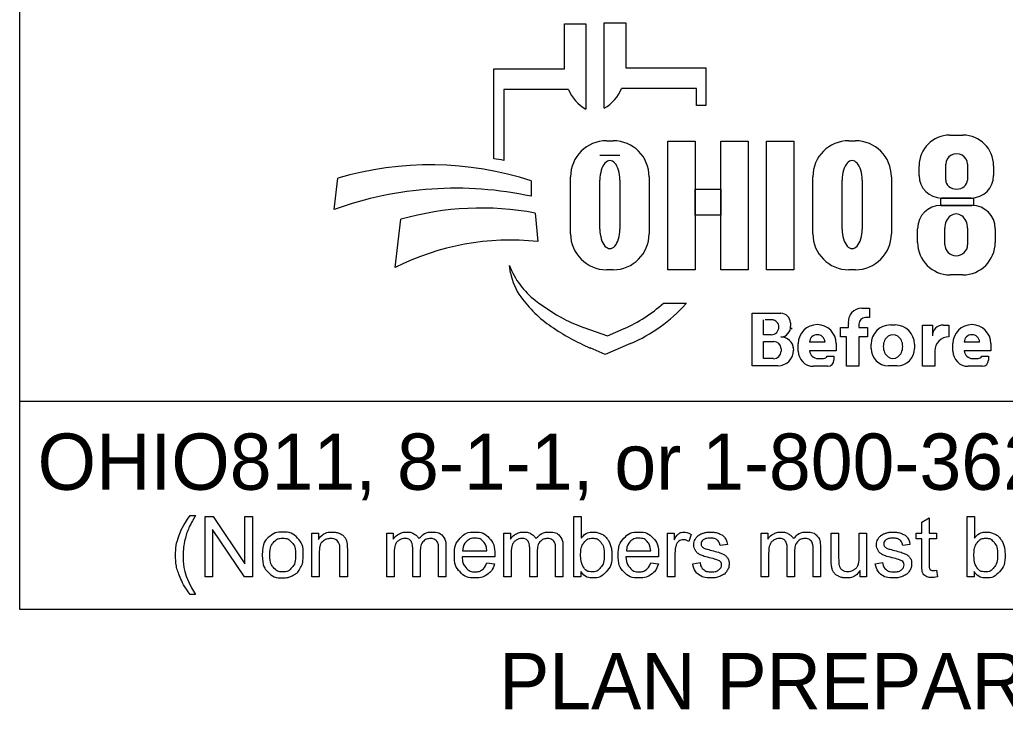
# Model space of a CAD drawing. Extents: x 0 to 84, y -106 to 22.
# Drawn here: x 2.912 to 5.365, y 2.808 to 4.523 of the extents above; entities that cross this region are included whole.
import ezdxf

# ---------------------------------------------------------------- set-up
doc = ezdxf.new("R2010")
doc.units = 0
doc.layers.add('CS-ANNO', color=7, linetype='Continuous')
doc.layers.add('CS-ANNO-MATC', color=7, linetype='Continuous')

msp = doc.modelspace()

# ---------------------------------------------------------------- linework, layer by layer
at = {"layer": 'CS-ANNO'}
for p, q in [((2.9116, 3.0559), (2.9116, 5.3934)), ((7.1616, 3.5737), (2.9116, 3.5737)), ((7.1616, 3.0559), (2.9116, 3.0559))]:
    msp.add_line(p, q, dxfattribs=at)
at = {"layer": 'CS-ANNO-MATC'}
for p, q in [((4.367, 4.3031), (4.367, 4.5152)), ((4.367, 4.5152), (4.4206, 4.5152)), ((4.4206, 4.5152), (4.4206, 4.4037)), ((4.2676, 4.4014), (4.2676, 4.5129)), ((4.2676, 4.5129), (4.3213, 4.5129)), ((4.3213, 4.5129), (4.3213, 4.3008)), ((4.0917, 4.1775), (4.0917, 4.4014)), ((4.0917, 4.4014), (4.2676, 4.4014)), ((4.4206, 4.4037), (4.6198, 4.4037)), ((4.6198, 4.4037), (4.6198, 4.3099)), ((4.1169, 4.3499), (4.1169, 4.1731)), ((4.2781, 4.3499), (4.1169, 4.3499)), ((4.5966, 4.3523), (4.4102, 4.3523)), ((4.5966, 4.3099), (4.5966, 4.3523)), ((4.6198, 4.3099), (4.5966, 4.3099)), ((4.3726, 4.2222), (4.3892, 4.2222)), ((4.9757, 4.2222), (4.9922, 4.2222)), ((5.2272, 4.2362), (5.2599, 4.2362)), ((4.4059, 4.1852), (4.3561, 4.1852)), ((5.1509, 4.1356), (5.1509, 4.1599)), ((5.2171, 4.1242), (5.2171, 4.1635)), ((5.2712, 4.1635), (5.2712, 4.1242)), ((5.3363, 4.1599), (5.3363, 4.1356)), ((3.6943, 4.0512), (3.7037, 4.1293)), ((4.185, 4.1228), (4.185, 4.084)), ((4.2832, 3.9907), (4.2832, 4.1327)), ((4.3561, 4.0021), (4.3561, 4.1245)), ((4.4059, 4.1245), (4.4059, 4.0021)), ((4.4786, 4.1327), (4.4786, 3.9907)), ((4.8862, 3.9907), (4.8862, 4.1327)), ((4.9591, 4.0021), (4.9591, 4.1245)), ((5.0089, 4.1245), (5.0089, 4.0021)), ((5.0817, 4.1327), (5.0817, 3.9907)), ((5.2803, 4.0796), (5.2069, 4.0796)), ((5.2051, 4.0613), (5.2824, 4.0613)), ((3.8461, 3.9067), (3.8608, 4.0268)), ((4.1949, 4.0422), (4.2012, 3.9713)), ((5.1472, 3.9694), (5.1472, 4.0034)), ((5.2147, 3.9634), (5.2147, 4.0043)), ((5.2715, 4.0043), (5.2715, 3.9634)), ((5.3403, 4.0034), (5.3403, 3.9694)), ((4.1338, 3.8938), (4.1308, 3.9117)), ((4.3892, 3.9013), (4.3726, 3.9013)), ((4.9922, 3.9013), (4.9757, 3.9013)), ((5.2593, 3.8884), (5.2282, 3.8884)), ((4.5141, 3.8179), (4.5716, 3.8179)), ((5.008, 3.8057), (5.0275, 3.8057)), ((5.0275, 3.8057), (5.0275, 3.7827)), ((4.7354, 3.6621), (4.7354, 3.7929)), ((4.7354, 3.7929), (4.8066, 3.7929)), ((5.0275, 3.7822), (5.0173, 3.7822)), ((4.3157, 3.7575), (4.3751, 3.737)), ((4.3751, 3.737), (4.4162, 3.7548)), ((4.7634, 3.7394), (4.7634, 3.7763)), ((4.7886, 3.7763), (4.7673, 3.7763)), ((4.8304, 3.7691), (4.8304, 3.7612)), ((4.9554, 3.7343), (4.9554, 3.7573)), ((4.9554, 3.7573), (4.9747, 3.7573)), ((4.9747, 3.7573), (4.9747, 3.7677)), ((5.0008, 3.7657), (5.0008, 3.7573)), ((5.0008, 3.7573), (5.0224, 3.7573)), ((5.0224, 3.7573), (5.0224, 3.7343)), ((5.0792, 3.7638), (5.0914, 3.7638)), ((5.1595, 3.6609), (5.1595, 3.7636)), ((5.1595, 3.7636), (5.184, 3.7636)), ((5.184, 3.7636), (5.184, 3.7367)), ((5.2113, 3.7636), (5.2251, 3.7636)), ((5.2251, 3.7636), (5.2251, 3.734)), ((4.7828, 3.7394), (4.7634, 3.7394)), ((4.9703, 3.7343), (4.9554, 3.7343)), ((4.9703, 3.6609), (4.9703, 3.7343)), ((5.0224, 3.7343), (5.0008, 3.7343)), ((5.0008, 3.7343), (5.0008, 3.6609)), ((4.3691, 3.69), (4.3318, 3.7065)), ((4.4324, 3.7175), (4.3691, 3.69)), ((4.7634, 3.68), (4.7634, 3.7228)), ((4.7634, 3.7228), (4.7889, 3.7228)), ((4.85, 3.6989), (4.85, 3.7173)), ((4.9165, 3.7213), (4.878, 3.7213)), ((4.9445, 3.7173), (4.9445, 3.6997)), ((5.0314, 3.7052), (5.0314, 3.716)), ((5.1392, 3.716), (5.1392, 3.7052)), ((5.2349, 3.6989), (5.2349, 3.7173)), ((5.3015, 3.7213), (5.2629, 3.7213)), ((5.3294, 3.7173), (5.3294, 3.6997)), ((4.807, 3.7047), (4.807, 3.6983)), ((4.8384, 3.7018), (4.8384, 3.7015)), ((4.9445, 3.6997), (4.8781, 3.6997)), ((4.9217, 3.686), (4.9386, 3.686)), ((4.9386, 3.686), (4.9386, 3.6762)), ((5.19, 3.6991), (5.19, 3.6609)), ((5.3294, 3.6997), (5.263, 3.6997)), ((5.3066, 3.686), (5.3235, 3.686)), ((5.3235, 3.686), (5.3235, 3.6762)), ((4.7991, 3.6621), (4.7354, 3.6621)), ((4.7887, 3.68), (4.7634, 3.68)), ((4.9233, 3.6609), (4.8879, 3.6609)), ((4.899, 3.6804), (4.9131, 3.6804)), ((5.0008, 3.6609), (4.9703, 3.6609)), ((5.0964, 3.6625), (5.0742, 3.6625)), ((5.19, 3.6609), (5.1595, 3.6609)), ((5.3083, 3.6609), (5.2729, 3.6609)), ((5.2839, 3.6804), (5.298, 3.6804))]:
    msp.add_line(p, q, dxfattribs=at)
for points in [[(4.5251, 4.2212), (4.593, 4.2212), (4.593, 3.9012), (4.5251, 3.9012)], [(4.6572, 4.2212), (4.7252, 4.2212), (4.7252, 3.9012), (4.6572, 3.9012)], [(4.7705, 4.2212), (4.8393, 4.2212), (4.8393, 3.9012), (4.7705, 3.9012)], [(4.593, 4.1013), (4.6572, 4.1013), (4.6572, 4.0373), (4.593, 4.0373)], [(5.2048, 4.0796), (5.2864, 4.0796), (5.2864, 4.0611), (5.2048, 4.0611)]]:
    msp.add_lwpolyline(points, close=True, dxfattribs=at)
for points in [[(3.3362, 3.2897), (3.3494, 3.2897)], [(3.373, 3.137), (3.373, 3.2872), (3.3933, 3.2872), (3.4723, 3.1692), (3.4723, 3.2872), (3.4913, 3.2872), (3.4913, 3.137), (3.471, 3.137), (3.392, 3.2549), (3.392, 3.137), (3.373, 3.137)], [(4.3084, 3.137), (4.2914, 3.137), (4.2914, 3.2872), (4.3098, 3.2872), (4.3098, 3.2337)], [(5.1574, 3.1689), (5.1574, 3.2315), (5.1438, 3.2315), (5.1438, 3.2458), (5.1574, 3.2458), (5.1574, 3.2728), (5.1758, 3.2839), (5.1758, 3.2458), (5.1942, 3.2458), (5.1942, 3.2315), (5.1758, 3.2315), (5.1758, 3.1678)], [(5.2875, 3.137), (5.2704, 3.137), (5.2704, 3.2872), (5.2889, 3.2872), (5.2889, 3.2337)], [(3.6389, 3.137), (3.6389, 3.2458), (3.6555, 3.2458), (3.6555, 3.2304)], [(3.8253, 3.137), (3.8253, 3.2458), (3.8418, 3.2458), (3.8418, 3.2305)], [(4.1167, 3.137), (4.1167, 3.2458), (4.1332, 3.2458), (4.1332, 3.2305)], [(4.5245, 3.137), (4.5245, 3.2458), (4.5411, 3.2458), (4.5411, 3.2294)], [(4.5836, 3.2424), (4.5771, 3.2253)], [(4.7577, 3.137), (4.7577, 3.2458), (4.7742, 3.2458), (4.7742, 3.2305)], [(4.932, 3.1785), (4.932, 3.2458), (4.9505, 3.2458), (4.9505, 3.1855)], [(5.0017, 3.1876), (5.0017, 3.2458), (5.0202, 3.2458), (5.0202, 3.137), (5.0037, 3.137)], [(4.6735, 3.2177), (4.6554, 3.2153)], [(5.1281, 3.2177), (5.11, 3.2153)], [(3.6574, 3.1964), (3.6574, 3.137), (3.6389, 3.137)], [(3.7273, 3.2039), (3.7273, 3.137), (3.7089, 3.137), (3.7089, 3.2032)], [(3.8438, 3.1934), (3.8438, 3.137), (3.8253, 3.137)], [(3.9084, 3.2002), (3.9084, 3.137), (3.89, 3.137), (3.89, 3.2077)], [(3.9729, 3.2117), (3.9729, 3.137), (3.9544, 3.137), (3.9544, 3.2055)], [(4.014, 3.2018), (4.0747, 3.2018)], [(4.1351, 3.1934), (4.1351, 3.137), (4.1167, 3.137)], [(4.1998, 3.2002), (4.1998, 3.137), (4.1814, 3.137), (4.1814, 3.2077)], [(4.2642, 3.2117), (4.2642, 3.137), (4.2458, 3.137), (4.2458, 3.2055)], [(4.422, 3.2018), (4.4827, 3.2018)], [(4.5429, 3.194), (4.5429, 3.137), (4.5245, 3.137)], [(4.7761, 3.1934), (4.7761, 3.137), (4.7577, 3.137)], [(4.8408, 3.2002), (4.8408, 3.137), (4.8224, 3.137), (4.8224, 3.2077)], [(4.9052, 3.2117), (4.9052, 3.137), (4.8868, 3.137), (4.8868, 3.2055)], [(4.0941, 3.1867), (4.0129, 3.1867)], [(4.0745, 3.1721), (4.0936, 3.1697)], [(4.5021, 3.1867), (4.4209, 3.1867)], [(4.4825, 3.1721), (4.5016, 3.1697)], [(4.5871, 3.1695), (4.6053, 3.1724)], [(5.0417, 3.1695), (5.0599, 3.1724)], [(4.3084, 3.1506), (4.3084, 3.137)], [(5.0037, 3.137), (5.0037, 3.1531)], [(5.1942, 3.1534), (5.1969, 3.1372)], [(5.2875, 3.1506), (5.2875, 3.137)], [(3.3494, 3.0928), (3.3362, 3.0928)]]:
    msp.add_lwpolyline(points, dxfattribs=at)
for centre, radius, start, end in [((4.3694, 4.3867), 0.0985, 201.9296, 240.7469), ((4.3188, 4.389), 0.0985, 299.2531, 338.0704), ((4.3726, 4.1327), 0.0895, 90, 180), ((4.3892, 4.1327), 0.0895, 0, 90), ((4.9757, 4.1327), 0.0895, 90, 180), ((4.9922, 4.1327), 0.0895, 0, 90), ((5.2272, 4.1599), 0.0763, 90, 180), ((5.2599, 4.1599), 0.0763, 0, 90), ((3.9636, 3.3685), 0.8191, 79.2074, 81.0007), ((3.9338, 3.3432), 0.8191, 72.1402, 106.3144), ((5.2069, 4.1356), 0.056, 180, 270), ((5.2803, 4.1356), 0.056, 270, 0), ((3.9969, 3.2121), 0.8919, 77.8238, 109.8274), ((4.0608, 3.3225), 0.7322, 79.44, 105.8467), ((5.2051, 4.0034), 0.0579, 90, 180), ((5.2824, 4.0034), 0.0579, 0, 90), ((4.3726, 3.9907), 0.0895, 180, 270), ((4.3892, 3.9907), 0.0895, 270, 0), ((4.9757, 3.9907), 0.0895, 180, 270), ((4.9922, 3.9907), 0.0895, 270, 0), ((4.1328, 3.3392), 0.6357, 83.8248, 116.8021), ((5.2282, 3.9694), 0.081, 180, 270), ((5.2593, 3.9694), 0.081, 270, 0), ((4.3182, 3.9838), 0.2008, 201.0457, 232.5314), ((4.2751, 3.9179), 0.1433, 189.6817, 216.0884), ((4.4088, 4.0153), 0.3088, 216.0884, 235.7167), ((4.5107, 4.235), 0.5173, 232.5314, 241.794), ((4.2728, 4.0853), 0.3602, 293.4582, 312.0712), ((4.2728, 4.0853), 0.401, 293.4582, 317.8286), ((5.008, 3.7721), 0.0335, 90, 187.5187), ((4.4255, 4.0762), 0.3371, 241.794, 250.9821), ((4.8066, 3.7691), 0.0238, 0, 90), ((5.0173, 3.7657), 0.0165, 90, 180), ((4.5753, 4.2596), 0.6044, 235.7167, 246.2325), ((4.7828, 3.7581), 0.0187, 270, 2.0582), ((4.7847, 3.7594), 0.0169, 357.8325, 90), ((4.8062, 3.7584), 0.0243, 270, 6.6529), ((4.8168, 3.7569), 0.0175, 347.4023, 0), ((4.8972, 3.7173), 0.0473, 0, 180), ((5.0792, 3.716), 0.0478, 90, 180), ((5.0914, 3.716), 0.0478, 0, 90), ((5.2109, 3.7367), 0.0269, 89.2449, 180), ((5.2822, 3.7173), 0.0473, 0, 180), ((4.8063, 3.702), 0.0321, 4.0748, 90), ((4.8973, 3.7203), 0.0193, 2.9632, 177.0368), ((5.2249, 3.6991), 0.0349, 89.6033, 180), ((5.2822, 3.7203), 0.0193, 2.9632, 177.0368), ((4.7889, 3.7047), 0.0181, 0, 90), ((4.8055, 3.7018), 0.033, 0, 11.7502), ((5.0742, 3.7052), 0.0428, 180, 270), ((5.0964, 3.7052), 0.0428, 270, 0), ((4.7887, 3.6983), 0.0184, 270, 0), ((4.7991, 3.7015), 0.0393, 270, 0), ((4.8879, 3.6989), 0.038, 180, 270), ((4.899, 3.7014), 0.021, 184.827, 270), ((4.9131, 3.6898), 0.00938, 270, 335.9979), ((5.2729, 3.6989), 0.038, 180, 270), ((5.2839, 3.7014), 0.021, 184.827, 270), ((5.298, 3.6898), 0.00938, 270, 335.9979), ((4.9233, 3.6762), 0.0152, 270, 0), ((5.3083, 3.6762), 0.0152, 270, 0)]:
    msp.add_arc(centre, radius, start, end, dxfattribs=at)
for centre, major_axis, ratio, start_param, end_param in [((4.381, 4.1245), (0, 0.0484), 0.514403, 4.712389, 7.853982), ((4.984, 4.1245), (0, 0.0484), 0.514403, 4.712389, 7.853982), ((5.2441, 4.1635), (0.0271, 0), 0.969373, 0, 3.141593), ((5.2441, 4.1242), (0.0271, 0), 0.818453, 3.141593, 6.283185), ((5.2431, 4.0043), (0, 0.0358), 0.794529, 4.712389, 7.853982), ((4.381, 4.0021), (0, 0.0484), 0.514403, 1.570796, 4.712389), ((4.984, 4.0021), (0, 0.0484), 0.514403, 1.570796, 4.712389), ((5.2431, 3.9634), (0.0284, 0), 0.959837, 3.141593, 6.283185), ((5.0858, 3.7106), (0, 0.029), 0.832186, 4.712389, 7.853982), ((5.0858, 3.7106), (0, 0.0302), 0.797287, 1.570796, 4.712389)]:
    msp.add_ellipse(centre, major_axis=major_axis, ratio=ratio, start_param=start_param, end_param=end_param, dxfattribs=at)
for points in [[(3.3362, 3.0928), (3.321, 3.1121), (3.3104, 3.1379), (3.2998, 3.1637), (3.2998, 3.1914), (3.2998, 3.2157), (3.3077, 3.2381), (3.317, 3.264), (3.3362, 3.2897)], [(3.3494, 3.2897), (3.337, 3.2684), (3.333, 3.2593), (3.3268, 3.2451), (3.3232, 3.2298), (3.3188, 3.2106), (3.3188, 3.1913), (3.3188, 3.142), (3.3494, 3.0928)], [(3.5155, 3.1914), (3.5155, 3.2216), (3.5322, 3.2362), (3.5463, 3.2483), (3.5664, 3.2483), (3.5889, 3.2483), (3.6031, 3.2336), (3.6173, 3.2189), (3.6173, 3.193), (3.6173, 3.172), (3.611, 3.1599), (3.6047, 3.1479), (3.5927, 3.1413), (3.5807, 3.1346), (3.5664, 3.1346), (3.5436, 3.1346), (3.5295, 3.1493), (3.5155, 3.1639), (3.5155, 3.1914)], [(3.6555, 3.2304), (3.6675, 3.2483), (3.6901, 3.2483), (3.7, 3.2483), (3.7082, 3.2447), (3.7164, 3.2412), (3.7205, 3.2354), (3.7246, 3.2297), (3.7263, 3.2218), (3.7273, 3.2167), (3.7273, 3.2039)], [(3.8418, 3.2305), (3.847, 3.2385), (3.8555, 3.2434), (3.864, 3.2483), (3.8748, 3.2483), (3.8869, 3.2483), (3.8947, 3.2432), (3.9024, 3.2382), (3.9056, 3.2292), (3.9185, 3.2483), (3.9392, 3.2483), (3.9554, 3.2483), (3.9641, 3.2393), (3.9729, 3.2303), (3.9729, 3.2117)], [(4.0936, 3.1697), (4.0891, 3.153), (4.0769, 3.1438), (4.0647, 3.1346), (4.0458, 3.1346), (4.0219, 3.1346), (4.0079, 3.1493), (3.9939, 3.164), (3.9939, 3.1905), (3.9939, 3.2179), (4.0081, 3.2331), (4.0222, 3.2483), (4.0447, 3.2483), (4.0665, 3.2483), (4.0804, 3.2334), (4.0942, 3.2185), (4.0942, 3.1916), (4.0942, 3.19), (4.0941, 3.1867)], [(4.1332, 3.2305), (4.1383, 3.2385), (4.1468, 3.2434), (4.1553, 3.2483), (4.1662, 3.2483), (4.1783, 3.2483), (4.186, 3.2432), (4.1938, 3.2382), (4.1969, 3.2292), (4.2099, 3.2483), (4.2306, 3.2483), (4.2468, 3.2483), (4.2555, 3.2393), (4.2642, 3.2303), (4.2642, 3.2117)], [(4.3098, 3.2337), (4.3215, 3.2483), (4.3396, 3.2483), (4.3496, 3.2483), (4.3586, 3.2442), (4.3676, 3.2402), (4.3733, 3.2328), (4.3791, 3.2255), (4.3824, 3.2152), (4.3857, 3.2048), (4.3857, 3.1931), (4.3857, 3.1651), (4.3719, 3.1499), (4.358, 3.1346), (4.3387, 3.1346), (4.3194, 3.1346), (4.3084, 3.1506)], [(4.5016, 3.1697), (4.4971, 3.153), (4.4849, 3.1438), (4.4727, 3.1346), (4.4538, 3.1346), (4.4299, 3.1346), (4.4159, 3.1493), (4.4019, 3.164), (4.4019, 3.1905), (4.4019, 3.2179), (4.4161, 3.2331), (4.4302, 3.2483), (4.4527, 3.2483), (4.4745, 3.2483), (4.4884, 3.2334), (4.5022, 3.2185), (4.5022, 3.1916), (4.5022, 3.19), (4.5021, 3.1867)], [(4.5411, 3.2294), (4.5474, 3.2409), (4.5528, 3.2446), (4.5582, 3.2483), (4.5646, 3.2483), (4.5739, 3.2483), (4.5836, 3.2424)], [(4.6053, 3.1724), (4.6068, 3.1614), (4.6139, 3.1556), (4.6209, 3.1497), (4.6336, 3.1497), (4.6463, 3.1497), (4.6525, 3.1549), (4.6586, 3.1601), (4.6586, 3.1671), (4.6586, 3.1733), (4.6532, 3.1769), (4.6494, 3.1794), (4.6343, 3.1832), (4.614, 3.1883), (4.6061, 3.192), (4.5983, 3.1958), (4.5942, 3.2024), (4.5902, 3.209), (4.5902, 3.2169), (4.5902, 3.2242), (4.5935, 3.2304), (4.5969, 3.2366), (4.6026, 3.2407), (4.6069, 3.2439), (4.6144, 3.2461), (4.6218, 3.2483), (4.6303, 3.2483), (4.6431, 3.2483), (4.6528, 3.2446), (4.6625, 3.2409), (4.6671, 3.2346), (4.6718, 3.2283), (4.6735, 3.2177)], [(4.7742, 3.2305), (4.7793, 3.2385), (4.7878, 3.2434), (4.7963, 3.2483), (4.8072, 3.2483), (4.8193, 3.2483), (4.827, 3.2432), (4.8348, 3.2382), (4.8379, 3.2292), (4.8509, 3.2483), (4.8716, 3.2483), (4.8878, 3.2483), (4.8965, 3.2393), (4.9052, 3.2303), (4.9052, 3.2117)], [(5.0599, 3.1724), (5.0614, 3.1614), (5.0685, 3.1556), (5.0755, 3.1497), (5.0881, 3.1497), (5.1009, 3.1497), (5.107, 3.1549), (5.1132, 3.1601), (5.1132, 3.1671), (5.1132, 3.1733), (5.1078, 3.1769), (5.1039, 3.1794), (5.0889, 3.1832), (5.0686, 3.1883), (5.0607, 3.192), (5.0529, 3.1958), (5.0488, 3.2024), (5.0448, 3.209), (5.0448, 3.2169), (5.0448, 3.2242), (5.0481, 3.2304), (5.0514, 3.2366), (5.0572, 3.2407), (5.0615, 3.2439), (5.0689, 3.2461), (5.0764, 3.2483), (5.0849, 3.2483), (5.0977, 3.2483), (5.1074, 3.2446), (5.1171, 3.2409), (5.1217, 3.2346), (5.1263, 3.2283), (5.1281, 3.2177)], [(5.2889, 3.2337), (5.3005, 3.2483), (5.3187, 3.2483), (5.3287, 3.2483), (5.3377, 3.2442), (5.3466, 3.2402), (5.3524, 3.2328), (5.3582, 3.2255), (5.3615, 3.2152), (5.3647, 3.2048), (5.3647, 3.1931), (5.3647, 3.1651), (5.3509, 3.1499), (5.3371, 3.1346), (5.3177, 3.1346), (5.2985, 3.1346), (5.2875, 3.1506)], [(3.5345, 3.1914), (3.5345, 3.1705), (3.5435, 3.1601), (3.5526, 3.1497), (3.5664, 3.1497), (3.5801, 3.1497), (3.5892, 3.1602), (3.5983, 3.1706), (3.5983, 3.192), (3.5983, 3.2122), (3.5892, 3.2226), (3.58, 3.233), (3.5664, 3.233), (3.5526, 3.233), (3.5435, 3.2227), (3.5345, 3.2123), (3.5345, 3.1914)], [(3.7089, 3.2032), (3.7089, 3.2144), (3.7067, 3.22), (3.7046, 3.2256), (3.6991, 3.2289), (3.6936, 3.2322), (3.6862, 3.2322), (3.6745, 3.2322), (3.6659, 3.2248), (3.6574, 3.2173), (3.6574, 3.1964)], [(3.89, 3.2077), (3.89, 3.2199), (3.8855, 3.2261), (3.881, 3.2322), (3.8707, 3.2322), (3.8629, 3.2322), (3.8563, 3.2281), (3.8497, 3.224), (3.8467, 3.2162), (3.8438, 3.2083), (3.8438, 3.1934)], [(3.9544, 3.2055), (3.9544, 3.2166), (3.9526, 3.2214), (3.9509, 3.2263), (3.9461, 3.2293), (3.9414, 3.2322), (3.9351, 3.2322), (3.9236, 3.2322), (3.916, 3.2246), (3.9084, 3.217), (3.9084, 3.2002)], [(4.0747, 3.2018), (4.0735, 3.2156), (4.0678, 3.2225), (4.059, 3.2331), (4.0449, 3.2331), (4.0322, 3.2331), (4.0236, 3.2246), (4.0149, 3.2161), (4.014, 3.2018)], [(4.1814, 3.2077), (4.1814, 3.2199), (4.1769, 3.2261), (4.1724, 3.2322), (4.1621, 3.2322), (4.1543, 3.2322), (4.1477, 3.2281), (4.1411, 3.224), (4.1381, 3.2162), (4.1351, 3.2083), (4.1351, 3.1934)], [(4.2458, 3.2055), (4.2458, 3.2166), (4.244, 3.2214), (4.2422, 3.2263), (4.2375, 3.2293), (4.2328, 3.2322), (4.2264, 3.2322), (4.215, 3.2322), (4.2074, 3.2246), (4.1998, 3.217), (4.1998, 3.2002)], [(4.3082, 3.1923), (4.3082, 3.1727), (4.3135, 3.164), (4.3222, 3.1497), (4.337, 3.1497), (4.3491, 3.1497), (4.3579, 3.1602), (4.3667, 3.1707), (4.3667, 3.1915), (4.3667, 3.2129), (4.3583, 3.223), (4.3498, 3.2331), (4.3379, 3.2331), (4.3258, 3.2331), (4.317, 3.2226), (4.3082, 3.2121), (4.3082, 3.1923)], [(4.4827, 3.2018), (4.4815, 3.2156), (4.4758, 3.2225), (4.467, 3.2331), (4.4529, 3.2331), (4.4402, 3.2331), (4.4315, 3.2246), (4.4229, 3.2161), (4.422, 3.2018)], [(4.5771, 3.2253), (4.5704, 3.2293), (4.5636, 3.2293), (4.5576, 3.2293), (4.5528, 3.2256), (4.548, 3.222), (4.546, 3.2155), (4.5429, 3.2057), (4.5429, 3.194)], [(4.6554, 3.2153), (4.6542, 3.2237), (4.6483, 3.2284), (4.6424, 3.2331), (4.6316, 3.2331), (4.6189, 3.2331), (4.6135, 3.2289), (4.608, 3.2247), (4.608, 3.2191), (4.608, 3.2155), (4.6103, 3.2126), (4.6126, 3.2096), (4.6174, 3.2077), (4.6201, 3.2067), (4.6337, 3.203), (4.6533, 3.1978), (4.661, 3.1944), (4.6688, 3.1911), (4.6732, 3.1848), (4.6776, 3.1784), (4.6776, 3.169), (4.6776, 3.1598), (4.6722, 3.1517), (4.6669, 3.1435), (4.6567, 3.1391), (4.6465, 3.1346), (4.6337, 3.1346), (4.6125, 3.1346), (4.6013, 3.1434), (4.5902, 3.1522), (4.5871, 3.1695)], [(4.8224, 3.2077), (4.8224, 3.2199), (4.8179, 3.2261), (4.8134, 3.2322), (4.8031, 3.2322), (4.7953, 3.2322), (4.7887, 3.2281), (4.7821, 3.224), (4.7791, 3.2162), (4.7761, 3.2083), (4.7761, 3.1934)], [(4.8868, 3.2055), (4.8868, 3.2166), (4.885, 3.2214), (4.8832, 3.2263), (4.8785, 3.2293), (4.8738, 3.2322), (4.8674, 3.2322), (4.856, 3.2322), (4.8484, 3.2246), (4.8408, 3.217), (4.8408, 3.2002)], [(5.11, 3.2153), (5.1088, 3.2237), (5.1029, 3.2284), (5.097, 3.2331), (5.0862, 3.2331), (5.0735, 3.2331), (5.0681, 3.2289), (5.0626, 3.2247), (5.0626, 3.2191), (5.0626, 3.2155), (5.0649, 3.2126), (5.0671, 3.2096), (5.072, 3.2077), (5.0747, 3.2067), (5.0883, 3.203), (5.1078, 3.1978), (5.1156, 3.1944), (5.1234, 3.1911), (5.1278, 3.1848), (5.1322, 3.1784), (5.1322, 3.169), (5.1322, 3.1598), (5.1268, 3.1517), (5.1214, 3.1435), (5.1113, 3.1391), (5.1011, 3.1346), (5.0883, 3.1346), (5.067, 3.1346), (5.0559, 3.1434), (5.0448, 3.1522), (5.0417, 3.1695)], [(5.2873, 3.1923), (5.2873, 3.1727), (5.2926, 3.164), (5.3013, 3.1497), (5.3161, 3.1497), (5.3282, 3.1497), (5.337, 3.1602), (5.3458, 3.1707), (5.3458, 3.1915), (5.3458, 3.2129), (5.3373, 3.223), (5.3289, 3.2331), (5.3169, 3.2331), (5.3049, 3.2331), (5.2961, 3.2226), (5.2873, 3.2121), (5.2873, 3.1923)], [(4.0129, 3.1867), (4.014, 3.1688), (4.0231, 3.1592), (4.0322, 3.1497), (4.0458, 3.1497), (4.056, 3.1497), (4.0632, 3.1551), (4.0703, 3.1604), (4.0745, 3.1721)], [(4.4209, 3.1867), (4.422, 3.1688), (4.4311, 3.1592), (4.4402, 3.1497), (4.4538, 3.1497), (4.464, 3.1497), (4.4712, 3.1551), (4.4783, 3.1604), (4.4825, 3.1721)], [(5.0037, 3.1531), (4.991, 3.1346), (4.9692, 3.1346), (4.9596, 3.1346), (4.9512, 3.1383), (4.9429, 3.142), (4.9388, 3.1476), (4.9348, 3.1532), (4.9332, 3.1612), (4.932, 3.1667), (4.932, 3.1785)], [(4.9505, 3.1855), (4.9505, 3.1711), (4.9516, 3.1661), (4.9533, 3.1588), (4.959, 3.1547), (4.9646, 3.1505), (4.9729, 3.1505), (4.9812, 3.1505), (4.9884, 3.1548), (4.9957, 3.159), (4.9987, 3.1663), (5.0017, 3.1737), (5.0017, 3.1876)], [(5.1969, 3.1372), (5.1891, 3.1355), (5.183, 3.1355), (5.1729, 3.1355), (5.1674, 3.1387), (5.1619, 3.1419), (5.1596, 3.1471), (5.1574, 3.1522), (5.1574, 3.1689)], [(5.1758, 3.1678), (5.1758, 3.1599), (5.1768, 3.1576), (5.1777, 3.1554), (5.1799, 3.154), (5.1821, 3.1527), (5.1862, 3.1527), (5.1892, 3.1527), (5.1942, 3.1534)]]:
    msp.add_open_spline(points, degree=3, dxfattribs=at)

# ---------------------------------------------------------------- texts
for s, p in [('OHIO811, 8-1-1, or 1-800-362-2764', (2.9561, 3.3537)), ('PLAN PREPARED BY:', (4.1053, 2.8076))]:
    msp.add_text(s, height=0.14, dxfattribs=at).set_placement(p)

doc.saveas('drawing.dxf')
